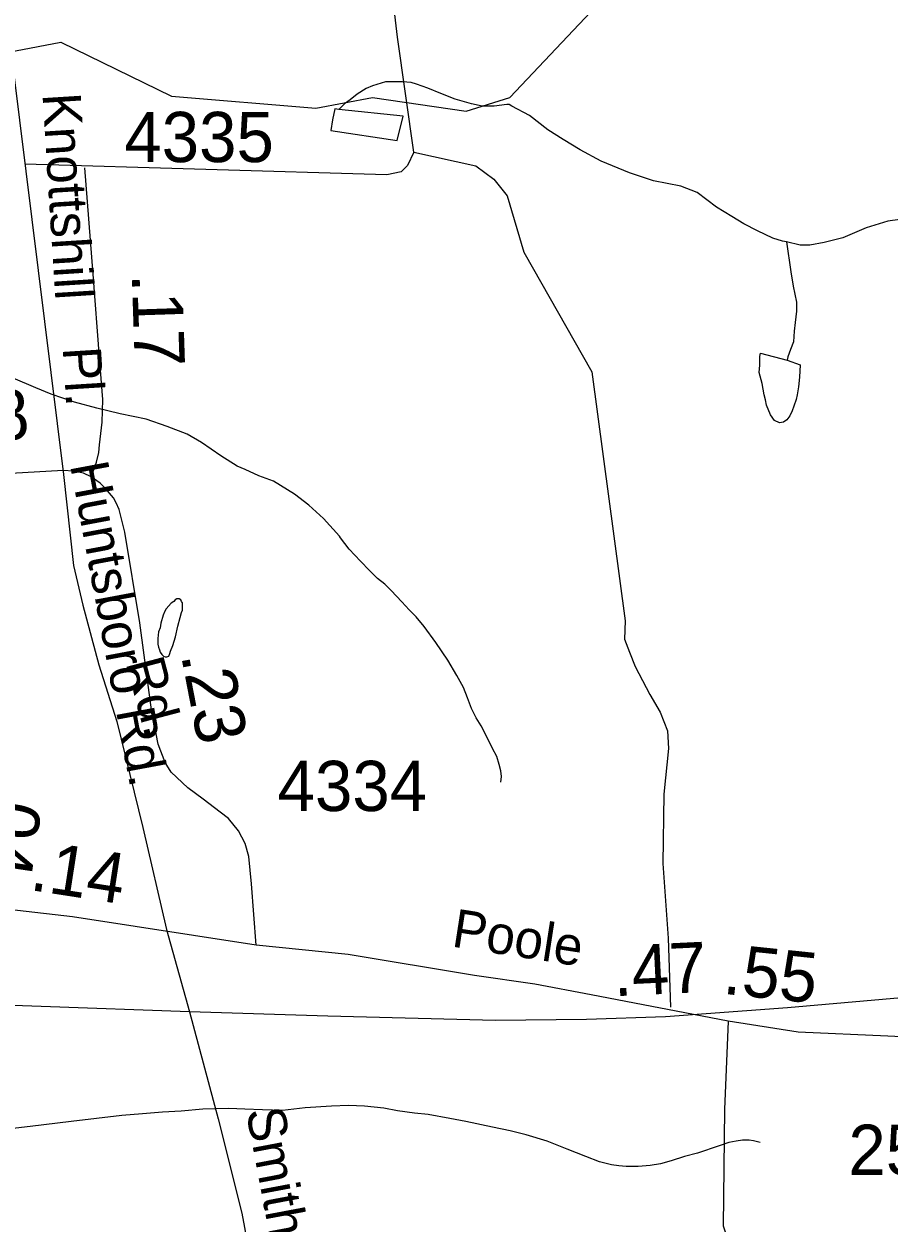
# Model space of a CAD drawing. Extents: x 2169602 to 2449496, y 721995 to 810662.
# Drawn here: x 2403896 to 2406048, y 791467 to 794450 of the extents above; entities that cross this region are included whole.
import ezdxf

# ---------------------------------------------------------------- set-up
doc = ezdxf.new("R2010")
doc.units = 0
doc.layers.add('Default', color=7, linetype='Continuous')

msp = doc.modelspace()

# ---------------------------------------------------------------- linework, layer by layer
at = {"layer": 'Default'}
for points in [[(2402890, 796628.5), (2403002.4, 796496.6), (2403153.1, 796318.6), (2403348.8, 796069.3), (2403430.4, 795914.4), (2403488.5, 795782.7), (2403522.5, 795652.6), (2403657.5, 795233.7), (2403718.2, 795036.9), (2403774.7, 794837.9), (2403816.5, 794636.9), (2403869.9, 794331.1), (2403915.9, 793964.6), (2403994.4, 793330.1), (2404019.5, 793103.9), (2404042.6, 793005.4), (2404082.3, 792856.8), (2404127.3, 792716.4), (2404192.2, 792452.6), (2404250.8, 792199.2), (2404308.3, 791993.9)], [(2404995.9, 794233.4), (2405104.8, 794267.2), (2405319.9, 794495.8), (2405475.9, 794830.5), (2405475.9, 794971.6), (2405886.9, 795832.5), (2406069, 796114.1), (2406225.8, 796291.4)], [(2404865.6, 794131.8), (2404825.3, 794417.9), (2404809.6, 794552.5), (2404809.6, 794725.3), (2404807.3, 794853.4), (2404809.6, 794911.7), (2404791.7, 794979.9)], [(2402651.3, 793741.6), (2403238.8, 794125), (2403704.9, 794351.7), (2403987.9, 794404.9), (2404262.9, 794271.3), (2404621.9, 794241.1), (2404763, 794267.7), (2404995.9, 794233.4)], [(2405097.4, 794250.1), (2405065.6, 794246), (2405035.5, 794246.1), (2405009.7, 794251.7), (2404969.1, 794263.5), (2404933.2, 794277.4), (2404901, 794291.2), (2404872.9, 794301.1), (2404859.2, 794304.8), (2404837.4, 794306.9), (2404819, 794306.8), (2404795.2, 794306.4), (2404763.4, 794296.2), (2404747, 794290.2), (2404725, 794276), (2404707.4, 794262.1), (2404693.5, 794252), (2404679.3, 794237.9)], [(2404663.5, 794211.9), (2404659.8, 794185.7), (2404824.1, 794160.9), (2404839.7, 794221), (2404679.3, 794237.9)], [(2404679.3, 794237.9), (2404669.3, 794239.8), (2404663.5, 794211.9)], [(2405793.2, 793908.5), (2405782.7, 793910.4), (2405758.9, 793918.1), (2405720.8, 793936), (2405686.7, 793953.7), (2405656.6, 793971.7), (2405618.9, 793995.2), (2405570.5, 794031), (2405530.1, 794046.8), (2405462.2, 794060.3), (2405402.1, 794079.9), (2405332, 794109.6), (2405279.9, 794137.3), (2405237.5, 794163.2), (2405199.3, 794186.9), (2405153.6, 794222.6), (2405109.5, 794246.3), (2405103.4, 794250.4), (2405097.4, 794250.1)], [(2404865.6, 794131.8), (2404849.9, 794098.1), (2404834.3, 794082.4), (2404798.4, 794075.7), (2403898.7, 794101.5)], [(2404865.6, 794131.8), (2405019.7, 794097.9), (2405065.2, 794064.9), (2405098.2, 794023.5), (2405139.6, 793882.9), (2405309, 793585.2), (2405391.8, 792966.3), (2405390, 792920.4), (2405402.2, 792888.5), (2405416.4, 792852.6), (2405452.8, 792782.9), (2405478.9, 792739), (2405497.2, 792693), (2405499.5, 792649.2), (2405488.1, 792535), (2405485, 792363.1), (2405498.2, 792177.3), (2405504.5, 792006.2)], [(2404063.6, 793324.4), (2404076.8, 793360.8), (2404082.7, 793385.2), (2404084.1, 793403.9), (2404091.1, 793460.3), (2404092.2, 793516.5), (2404083.9, 793621.4), (2404068.1, 793828.6), (2404047.2, 794092.9)], [(2406074.7, 793964), (2406044.8, 793959.7), (2405990.6, 793943.5), (2405933, 793919), (2405886.7, 793906.9), (2405850.8, 793900.6), (2405826.6, 793900.6), (2405793.2, 793908.5)], [(2405793.2, 793908.5), (2405803.2, 793834.3), (2405809.6, 793798.4), (2405818, 793758.7), (2405817.6, 793736.4), (2405814.3, 793708.5), (2405812.2, 793686.5), (2405810.4, 793660.4), (2405802.4, 793640.6), (2405796.4, 793622.4), (2405794.8, 793614.5)], [(2405794.8, 793614.5), (2405826.8, 793602.8), (2405825.2, 793572.6), (2405822.9, 793548.6), (2405819, 793528.5), (2405817.2, 793516.7), (2405811.4, 793500.5), (2405807.3, 793488.5), (2405801.4, 793476.4), (2405793.4, 793466.3), (2405785.2, 793460.6), (2405775.5, 793458.4), (2405763.2, 793464.3), (2405753.4, 793478.4), (2405743.3, 793502.2), (2405740.9, 793516), (2405737, 793528.3), (2405732.7, 793556.2), (2405725.1, 793584.1), (2405726.3, 793602.2), (2405726.5, 793624), (2405728.4, 793632.3), (2405794.8, 793614.5)], [(2404680.8, 793176.9), (2404641.1, 793220.7), (2404604.6, 793254.2), (2404568.7, 793281.5), (2404516.6, 793313.3), (2404480.5, 793326.9), (2404446.3, 793343), (2404426.4, 793350.9), (2404386, 793376.5), (2404338, 793410.1), (2404302.3, 793430.1), (2404252.1, 793449.9), (2404199.8, 793467.5), (2404135.6, 793481.2), (2404077.6, 793494.9), (2404021.6, 793510.2), (2403963.6, 793530), (2403925.4, 793545.9), (2403869, 793569.4)], [(2404063.6, 793324.4), (2404043.9, 793333.5), (2404019.4, 793338.5), (2403993.6, 793340.2), (2403659.6, 793320.9)], [(2404474.1, 792160), (2404462.4, 792312.2), (2404455.3, 792380.8), (2404446.6, 792412.5), (2404429.8, 792444.6), (2404405.3, 792475.2), (2404383.9, 792490.5), (2404341.6, 792522.8), (2404303.7, 792551.3), (2404262.3, 792589.7), (2404247.8, 792614.3), (2404230.3, 792660.1), (2404213.7, 792745.3), (2404184.1, 792961.5), (2404146.8, 793187), (2404133.2, 793243.2), (2404125.9, 793260.1), (2404118.7, 793272.1), (2404098.6, 793295.5), (2404085.7, 793308.3), (2404063.6, 793324.4)], [(2405082.1, 792565.4), (2405084.2, 792579.3), (2405082.1, 792593.4), (2405078, 792609.5), (2405072.1, 792629.4), (2405061.8, 792649.2), (2405053.8, 792665), (2405033.5, 792705), (2405021.2, 792725.1), (2405009.5, 792748.8), (2404999.3, 792774.7), (2404989.2, 792800.6), (2404973, 792830.6), (2404950.7, 792868.4), (2404920.7, 792912.3), (2404892, 792952.4), (2404871.7, 792976.1), (2404853.9, 792993.8), (2404836.1, 793013.9), (2404809.6, 793041.9), (2404794, 793057.6), (2404775.6, 793071.4), (2404755.5, 793091.4), (2404733.5, 793115.1), (2404705.2, 793144.8), (2404683.1, 793172.9), (2404680.8, 793176.9)], [(2404278.7, 792953), (2404284.4, 792974.9), (2404288.1, 792986.9), (2404290.3, 792993), (2404290.5, 793000.7), (2404290.3, 793004.8), (2404290.3, 793010.8), (2404288.1, 793014.8), (2404286.2, 793018.8), (2404282.3, 793021), (2404276.4, 793020.7), (2404272.3, 793018.9), (2404268.6, 793014.6), (2404262.5, 793010.6), (2404250.1, 792996.6), (2404246.3, 792990.7), (2404242.6, 792980.8), (2404236.6, 792960.6), (2404234.6, 792948.7), (2404230.9, 792938.8), (2404229, 792922.4), (2404229, 792914.7), (2404228.8, 792908.6), (2404230.9, 792900.6), (2404233.3, 792894.6), (2404235.2, 792888.6), (2404238.9, 792882.8), (2404243.4, 792878.8), (2404247.3, 792876.6), (2404251.2, 792876.8), (2404256.9, 792878.8), (2404259.2, 792884.9), (2404261, 792890.8), (2404266.8, 792904.9), (2404273.1, 792926.7), (2404278.7, 792953)], [(2404308.3, 791993.9), (2403569.1, 792021.1), (2403029.1, 792046.3), (2402806.3, 792056.7), (2402632.3, 792083.6), (2402291.4, 792148.9), (2402151.2, 792176.1), (2402000.5, 792197.1), (2401686.6, 792249.4), (2401458.3, 792272.9)], [(2404474.1, 792160), (2404017.1, 792230.8), (2403721.2, 792264.7)], [(2407324.2, 791881.1), (2406584.9, 791908.3), (2406045, 791933.4), (2405822.1, 791943.9), (2405648.1, 791970.8), (2405307.3, 792036.1), (2405167, 792063.3), (2405016.4, 792084.2), (2404702.4, 792136.6), (2404474.1, 792160)], [(2406814.4, 792112.2), (2406606.2, 792077.7), (2406314.8, 792049.4), (2405795.3, 792004.4), (2405491.8, 791981.4), (2405295.1, 791975.1), (2405069.1, 791973), (2404651.6, 791983.5), (2404308.3, 791993.9)], [(2404308.3, 791993.9), (2404379.5, 791728), (2404438.1, 791493.4), (2404497.7, 791173), (2404573.1, 790785.5), (2404676.7, 790251.5), (2404756.2, 789918.5), (2404805.4, 789704.9)], [(2405648.1, 791970.8), (2405638.4, 791751), (2405635.1, 791461.7), (2405661.9, 791384.3)], [(2405727.5, 791669.5), (2405711.1, 791673.2), (2405699.7, 791675.4), (2405683.5, 791675), (2405667.3, 791673), (2405649.2, 791669.2), (2405625.4, 791661.1), (2405571.7, 791642.4), (2405539.3, 791634.3), (2405505.7, 791624), (2405479.8, 791616.2), (2405454, 791611.9), (2405423.9, 791609.6), (2405394.1, 791609.6), (2405375.7, 791611.6), (2405357.8, 791613.5), (2405328.1, 791621.3), (2405293.9, 791634.9), (2405247.5, 791652.9), (2405197.7, 791672.6), (2405145.4, 791688.2), (2405105.4, 791697.9), (2405061.5, 791707.8), (2404995.3, 791721.4), (2404955.5, 791729.1), (2404901.4, 791738.9), (2404867.2, 791742.4), (2404825.1, 791748.4), (2404790.9, 791754.4), (2404742.9, 791760), (2404703.3, 791761.6), (2404660.9, 791759.5), (2404595.5, 791755.2), (2404539.3, 791748.6), (2404489.4, 791750.5), (2404445.6, 791752.3), (2404405.4, 791753.9), (2404341.2, 791751.8), (2404287.5, 791747.4), (2404241.1, 791745.1), (2404191.1, 791740.9), (2404139.4, 791736.5), (2404013.7, 791721.8), (2403911.8, 791709.3), (2403861.8, 791703)]]:
    msp.add_lwpolyline(points, dxfattribs=at)

# ---------------------------------------------------------------- texts
for s, height, rotation, p in [('Knottshill', 95, 273.608, (2403942.1, 794276.4)), ('.17', 125, 271.8988, (2404164.3, 793828.6)), ('Pl.', 95, 273.608, (2403992.4, 793645.4)), ('.08', 125, 3.7161, (2403680.6, 793404.3)), ('Huntsboro Rd.', 95, 280.5924, (2404010.6, 793353.7)), ('Rd.', 95, 284.8081, (2404149.1, 792862.3)), ('.23', 125, 280.9993, (2404286.5, 792881.4)), ('.04', 125, 261.5509, (2403824.1, 792571.2)), ('.14', 125, 351.1937, (2403908.1, 792297.5)), ('Poole', 95, 351.1864, (2404957.5, 792156.9)), ('.47', 125, 2.7278, (2405364.2, 792032.8)), ('.55', 125, 354.0223, (2405632, 792039.4)), ('Smithfield', 95, 280.6728, (2404448.2, 791748.2))]:
    msp.add_text(s, height=height, rotation=rotation, dxfattribs=at).set_placement(p)
for s, p in [('4335', (2404145.9, 794106.9)), ('4334', (2404527.1, 792493.4)), ('2506', (2405946.8, 791588.6))]:
    msp.add_text(s, height=125, dxfattribs=at).set_placement(p)

doc.saveas('drawing.dxf')
